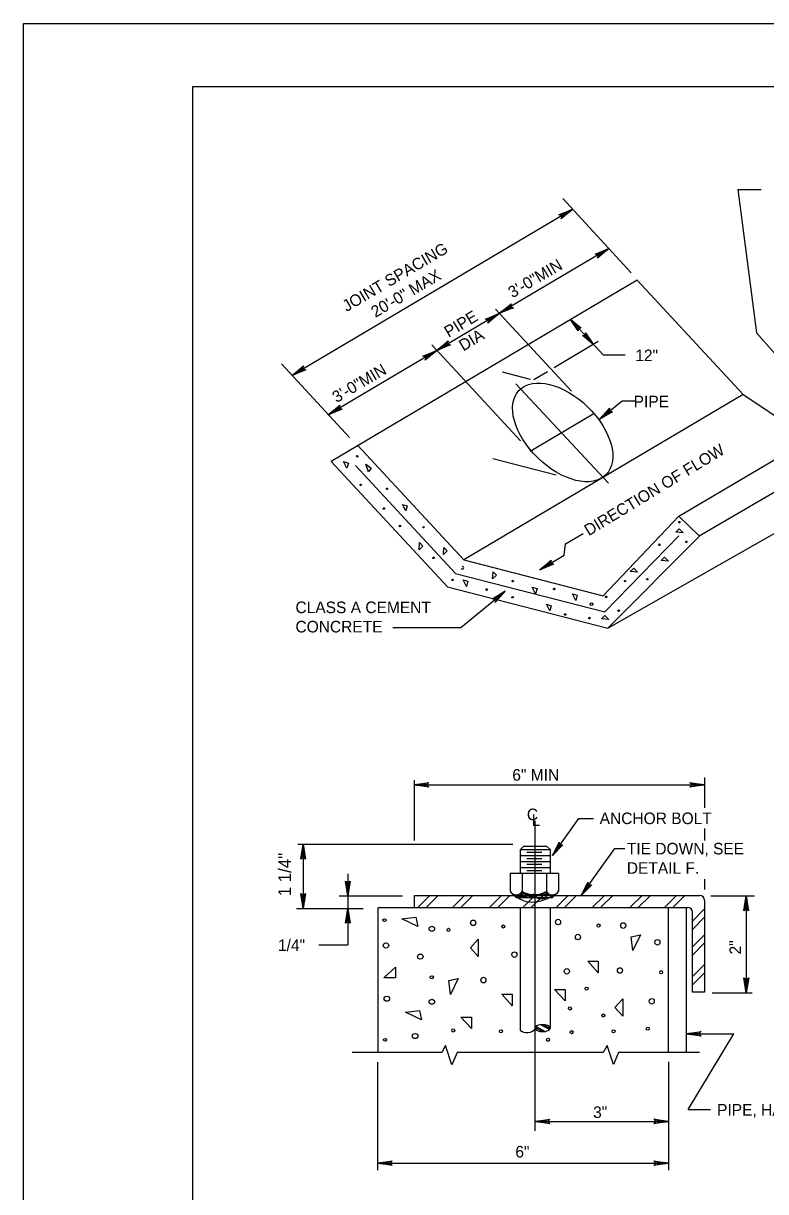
# Model space of a CAD drawing. Extents: x 5 to 910, y -47 to 547.
# Drawn here: x 4.7 to 180.3, y 270.9 to 547.5 of the extents above; entities that cross this region are included whole.
import ezdxf

# ---------------------------------------------------------------- set-up
doc = ezdxf.new("R2010")
doc.units = 0
for name, color, linetype in [('1', 7, 'Continuous'), ('2', 7, 'Continuous'), ('3', 7, 'Continuous'), ('PLT-BNDY', 7, 'Continuous')]:
    doc.layers.add(name, color=color, linetype=linetype)

msp = doc.modelspace()

# ---------------------------------------------------------------- linework, layer by layer
at = {"layer": '1'}
msp.add_lwpolyline([(830.72, -31.53), (830.72, 532.47), (44.72, 532.47), (44.72, -31.53), (830.72, -31.53), (830.72, -5.17), (630.72, -5.17), (630.72, 59.51), (830.72, 59.51), (830.72, 88.47), (630.72, 88.47), (630.72, -31.53), (709.52, -31.53), (709.52, -5.17), (709.52, -31.53), (786.52, -31.53), (786.52, -5.17), (786.52, -17.48), (830.72, -17.48)], dxfattribs=at)
for points in [[(81.6, 443.4), (81.25, 442.17), (80.45, 443.72)], [(85.76, 443.15), (87, 442.17), (86.38, 441.3)], [(95.53, 433.29), (95.19, 432.05), (94.39, 433.61)], [(159.86, 427.82), (160.78, 426.88), (159.04, 427.02)], [(99.21, 423.75), (98.3, 422.88), (98.41, 424.6)], [(104.98, 422.58), (104.06, 421.71), (104.18, 423.43)], [(156.39, 421.1), (157.3, 420.16), (155.56, 420.29)], [(116.62, 416.82), (115.71, 415.95), (115.82, 417.66)], [(149.09, 418.49), (150, 417.55), (148.26, 417.69)], [(109.87, 415.4), (109.53, 414.16), (108.73, 415.72)], [(126.21, 413.66), (125.87, 412.42), (125.07, 413.98)], [(135.73, 412.1), (135.38, 410.89), (134.58, 412.4)], [(129.57, 409.63), (129.23, 408.4), (128.43, 409.95)], [(142.27, 407.32), (143.19, 406.38), (141.45, 406.52)], [(94.25, 335.5), (97.56, 335.91), (98.02, 333.67)], [(112.32, 330.72), (112.32, 326.6), (110.44, 328.66)], [(148.88, 327.97), (148.47, 331.27), (150.71, 331.75)], [(92.76, 321.57), (89.99, 321.57), (92.76, 324.04)], [(140.71, 325.46), (140.71, 322.71), (138.24, 325.46)], [(105.73, 317.61), (105.32, 320.93), (107.58, 321.39)], [(132.84, 318.8), (132.84, 316.05), (130.37, 318.8)], [(120.33, 317.68), (120.33, 314.93), (117.86, 317.68)], [(146.5, 316.54), (146.5, 312.42), (144.65, 314.48)], [(95.09, 313.4), (98.41, 313.81), (98.87, 311.57)], [(110.7, 312.26), (110.7, 309.51), (108.23, 312.26)]]:
    msp.add_lwpolyline(points, close=True, dxfattribs=at)
for centre, major_axis in [((83.68, 445), (-0.132, 0.137)), ((84.52, 438.23), (-0.132, 0.137)), ((90.74, 437.29), (-0.116, 0.12)), ((89.98, 432.62), (-0.137, -0.132)), ((93.82, 428.5), (-0.137, -0.132)), ((159.85, 429.4), (0.131, -0.138)), ((99.37, 428.2), (-0.12, -0.116)), ((155.12, 424.05), (0.131, -0.138)), ((161.51, 424.73), (0.131, -0.138)), ((101.74, 420.96), (-0.137, -0.132)), ((106.2, 415.74), (-0.048, -0.184)), ((120.49, 415.45), (-0.048, -0.184)), ((147.01, 415.44), (-0.121, -0.115)), ((152.3, 415.89), (0.131, -0.138)), ((114.3, 413.43), (-0.048, -0.184)), ((130.28, 413.57), (-0.048, -0.184)), ((120.42, 411.61), (-0.042, -0.161)), ((139.08, 409.99), (-0.241, -0.229)), ((142.57, 411.72), (-0.048, -0.184)), ((132.87, 407.54), (-0.184, 0.048)), ((138.6, 406.69), (-0.048, -0.184)), ((145.53, 408.45), (-0.138, -0.131)), ((90.15, 335.19), (-0.381, 0)), ((111.11, 334.55), (0, -0.666)), ((131.19, 334.74), (0, -0.666)), ((101.33, 333.13), (-0.666, 0)), ((105.27, 332.87), (0, -0.381)), ((118.22, 333.69), (0, -0.381)), ((140.77, 333.9), (0, -0.381)), ((146.59, 333.91), (0, -0.666)), ((90.48, 329.18), (-0.666, 0)), ((135.88, 331.19), (0, -0.666)), ((154.68, 329.95), (0, -0.666)), ((98.6, 326.56), (-0.666, 0)), ((120.87, 327.03), (0, -0.666)), ((133.26, 323.07), (0, -0.666)), ((145.84, 323.27), (0, -0.666)), ((101.32, 321.67), (-0.381, 0)), ((113.54, 320.99), (0, -0.666)), ((155.59, 322.85), (0, -0.381)), ((137.95, 318.98), (0, -0.381)), ((90.69, 316.6), (-0.666, 0)), ((101.33, 315.86), (-0.666, 0)), ((153.36, 315.98), (0, -0.666)), ((133.99, 314.29), (0, -0.381)), ((141.88, 312.62), (0, -0.381)), ((152.4, 309.49), (0, -0.381)), ((90.26, 306.85), (-0.381, 0)), ((97.37, 307.76), (-0.666, 0)), ((106.4, 309.08), (0, -0.381)), ((117.67, 308.87), (0, -0.381)), ((128.83, 306.88), (0, -0.381)), ((134.39, 308.67), (0, -0.381)), ((144.33, 308.87), (0, -0.381))]:
    msp.add_ellipse(centre, major_axis=major_axis, ratio=0.9, dxfattribs=at)
msp.add_ellipse((108.57, 418.59), major_axis=(-0.322, 0.083), ratio=0.9, start_param=0.504724, end_param=5.232157, dxfattribs=at)
at = {"layer": '2'}
for p, q in [((173.7, 508.12), (179.24, 508.12)), ((134.65, 503.46), (68.26, 464.13)), ((132.3, 506.02), (148.49, 488.45)), ((143.23, 494.17), (117.33, 478.84)), ((149.91, 486.67), (77.52, 443.79)), ((149.91, 486.67), (174.96, 459.62)), ((117.29, 478.8), (102.48, 470.03)), ((116.42, 479.82), (134.35, 460.4)), ((134.17, 477.35), (141.87, 469.01)), ((178.09, 474.18), (208.3, 440.06)), ((101.36, 471.41), (122.32, 448.69)), ((140.71, 472.16), (130.24, 465.96)), ((102.48, 470.03), (76.84, 454.84)), ((141.87, 469.01), (147.07, 469.01)), ((65.76, 466.85), (81.85, 449.42)), ((117.95, 464.95), (124.61, 463.24)), ((128.68, 465.02), (125.45, 463.12)), ((159.77, 430.8), (219.81, 466.4)), ((121.24, 462.16), (143.12, 438.6)), ((174.96, 459.62), (108.87, 420.48)), ((174.96, 459.62), (190.66, 449.12)), ((141.03, 453.77), (146.34, 458.11)), ((146.34, 458.11), (149.36, 458.11)), ((164.58, 426.13), (217.93, 457.43)), ((139.5, 454.93), (124.63, 446.12)), ((83.82, 447.52), (108.87, 420.48)), ((77.52, 443.79), (105.02, 414.09)), ((83.31, 442.83), (106.97, 417.27)), ((115.73, 444.45), (130.76, 440.59)), ((142.36, 441.05), (142.36, 441.05)), ((142.93, 404.33), (196.77, 434.94)), ((159.77, 430.8), (141.84, 411.97)), ((159.77, 430.8), (164.65, 426.06)), ((132.94, 424.25), (137.1, 426.72)), ((159.73, 426.13), (142.22, 408.19)), ((164.65, 426.06), (142.93, 404.33)), ((132.64, 421.55), (132.98, 424.28)), ((108.87, 420.48), (141.84, 411.97)), ((126.85, 418.14), (132.64, 421.55)), ((106.97, 417.27), (142.22, 408.19)), ((105.02, 414.09), (142.93, 404.33)), ((108.23, 404.44), (118.71, 413.07)), ((92.14, 404.44), (108.23, 404.44)), ((97.13, 368.31), (97.13, 354.03)), ((165.86, 368.95), (165.86, 361.74)), ((97.13, 367.23), (165.86, 367.23)), ((125.77, 285.29), (125.77, 358.7)), ((129.85, 350.49), (136.11, 359.25)), ((136.11, 359.25), (139.61, 359.25)), ((165.86, 356.85), (165.86, 354.08)), ((69.61, 353.16), (120.49, 353.16)), ((70.91, 353.16), (70.91, 337.97)), ((122.2, 351.95), (129.34, 351.95)), ((122.2, 351.95), (122.2, 346.37)), ((122.3, 351.95), (123.1, 352.68)), ((123.1, 352.68), (128.45, 352.68)), ((123.78, 351.27), (127.33, 351.27)), ((129.34, 351.95), (128.45, 352.68)), ((129.34, 351.95), (129.34, 346.44)), ((136.65, 341.02), (144.6, 352.12)), ((144.6, 352.12), (146.96, 352.12)), ((122.2, 350.53), (129.34, 350.53)), ((122.2, 349.09), (129.34, 349.09)), ((123.78, 349.82), (127.33, 349.82)), ((81.46, 346.19), (81.46, 340.92)), ((131.29, 346.23), (119.85, 346.23)), ((119.85, 346.23), (119.85, 342)), ((122.2, 347.67), (129.34, 347.67)), ((122.71, 346.23), (122.71, 341.98)), ((123.78, 348.41), (127.33, 348.41)), ((123.78, 346.96), (127.33, 346.96)), ((128.43, 346.23), (128.43, 341.98)), ((131.29, 346.23), (131.29, 342.02)), ((165.86, 344.88), (165.86, 342.41)), ((79.42, 340.92), (94.38, 340.92)), ((81.46, 340.92), (81.46, 329.32)), ((97.2, 338.16), (97.2, 341.02)), ((97.2, 341.02), (164.74, 341.02)), ((98, 338.16), (100.86, 341.02)), ((99.97, 338.16), (102.83, 341.02)), ((106.21, 338.16), (109.07, 341.02)), ((108.18, 338.16), (111.04, 341.02)), ((114.97, 338.16), (117.83, 341.02)), ((116.94, 338.16), (119.8, 341.02)), ((120.37, 341.45), (121.29, 340.51)), ((121.29, 340.51), (129.85, 340.51)), ((122.84, 338.16), (125.7, 341.02)), ((124.81, 338.16), (127.67, 341.02)), ((130.76, 341.45), (129.85, 340.51)), ((130.74, 338.16), (133.6, 341.02)), ((132.71, 338.16), (135.57, 341.02)), ((139.29, 338.16), (142.15, 341.02)), ((141.26, 338.16), (144.12, 341.02)), ((148.19, 338.16), (151.05, 341.02)), ((150.16, 338.16), (153.02, 341.02)), ((156.36, 338.16), (159.22, 341.02)), ((158.33, 338.16), (161.19, 341.02)), ((167.34, 340.92), (177.62, 340.92)), ((175.72, 340.92), (175.72, 318.02)), ((69.31, 337.97), (85.12, 337.97)), ((88.6, 338.16), (161.88, 338.16)), ((88.6, 303.84), (88.6, 338.16)), ((122.2, 338.02), (122.2, 309.12)), ((129.34, 338.06), (129.34, 309.6)), ((157.23, 338.16), (157.23, 303.84)), ((161.51, 338.16), (161.51, 303.84)), ((162.97, 334.98), (165.83, 337.84)), ((165.83, 339.92), (165.83, 318.14)), ((162.97, 318.14), (162.97, 337.06)), ((162.97, 333.01), (165.83, 335.87)), ((74.62, 329.32), (81.46, 329.32)), ((162.97, 328.89), (165.83, 331.75)), ((162.97, 326.92), (165.83, 329.78)), ((162.97, 321.82), (165.83, 324.68)), ((162.97, 319.85), (165.83, 322.71)), ((165.83, 318.14), (162.97, 318.14)), ((167.64, 318.02), (177.09, 318.02)), ((125.8, 309.74), (127.56, 308.8)), ((125.98, 310.02), (128.15, 308.85)), ((127.05, 310.45), (129.14, 309.28)), ((127.65, 310.47), (129.32, 309.53)), ((161.51, 308.28), (172.73, 308.28)), ((103.72, 303.84), (82.46, 303.84)), ((88.46, 301.6), (88.46, 275.97)), ((141.88, 303.84), (107.36, 303.84)), ((164.64, 303.84), (145.52, 303.84)), ((157.32, 301.66), (157.32, 275.97)), ((161.95, 290.4), (167.28, 290.4)), ((125.77, 287.55), (157.32, 287.55)), ((88.46, 277.64), (157.32, 277.64))]:
    msp.add_line(p, q, dxfattribs=at)
for points in [[(175.31, 337.61), (175.53, 337.72), (175.72, 340.92), (175.31, 337.61), (175.15, 337.42), (175.72, 340.92), (175.88, 337.72), (176.11, 337.61), (175.72, 340.92), (176.27, 337.42), (176.11, 337.61)], [(107.36, 303.84), (106.1, 300.96), (104.59, 305.49), (103.72, 303.84)], [(145.52, 303.84), (144.28, 301), (142.77, 305.53), (141.88, 303.84)]]:
    msp.add_lwpolyline(points, dxfattribs=at)
for centre, radius, start, end in [((121.29, 342.82), 1.65, 209.0546, 331.645), ((125.53, 347.1), 5.88, 241.013, 299.4435), ((129.84, 342.82), 1.65, 211.9209, 330.9454), ((164.73, 339.92), 1.1, 0, 90), ((161.87, 337.06), 1.1, 0, 90)]:
    msp.add_arc(centre, radius, start, end, dxfattribs=at)
msp.add_ellipse((132.29, 450.65), major_axis=(10.28, -9.99), ratio=0.58964, dxfattribs=at)
for centre, major_axis, start_param, end_param in [((127.53, 309.45), (-1.88, 0), 3.352555, 6.084645), ((123.86, 309.62), (-1.87, 0), 0.486014, 2.941111), ((127.53, 309.82), (1.87, 0), 3.308332, 6.128868)]:
    msp.add_ellipse(centre, major_axis=major_axis, ratio=0.546749, start_param=start_param, end_param=end_param, dxfattribs=at)
for points in [[(121.01, 341.06), (121.47, 340.67), (129.57, 340.74), (130.21, 341.13), (129.34, 341.06), (128.79, 341.22), (128.43, 341.52), (128.34, 341.7), (127.51, 341.38), (126.51, 341.11), (125.86, 341.08), (125.89, 340.88), (128.38, 340.9), (128.31, 341.15), (127.03, 341.08), (128.24, 341.45), (128.79, 340.97)], [(121.29, 341.08), (121.59, 340.88), (125.38, 340.88), (125.52, 340.92), (125.54, 341.11), (124.77, 341.15), (123.92, 341.2), (123.37, 341.47), (122.71, 341.68), (122.18, 341.27), (121.82, 341.11), (121.47, 341.08), (121.61, 340.97), (123.85, 341.04), (122.89, 341.34), (122.32, 341.2), (122.78, 341.18)]]:
    msp.add_spline(points, degree=3, dxfattribs=at)
at = {"layer": '3'}
for p, q in [((173.7, 508.12), (178.09, 474.18)), ((161.95, 290.4), (172.73, 308.28))]:
    msp.add_line(p, q, dxfattribs=at)
for points in [[(131.59, 502.13), (131.81, 501.97), (134.65, 503.46), (131.59, 502.13), (131.36, 502.15), (134.65, 503.46), (131.97, 501.7), (132, 501.42), (134.65, 503.46), (131.93, 501.19), (132, 501.42)], [(140.17, 492.84), (140.39, 492.68), (143.23, 494.17), (140.17, 492.84), (139.94, 492.87), (143.23, 494.17), (140.55, 492.41), (140.58, 492.13), (143.23, 494.17), (140.51, 491.9), (140.58, 492.13)], [(114.22, 477.47), (114.45, 477.31), (117.29, 478.8), (114.22, 477.47), (113.99, 477.49), (117.29, 478.8), (114.61, 477.03), (114.63, 476.76), (117.29, 478.8), (114.56, 476.53), (114.63, 476.76)], [(120.4, 480.17), (120.17, 480.33), (117.33, 478.84), (120.4, 480.17), (120.63, 480.15), (117.33, 478.84), (120.01, 480.6), (119.99, 480.88), (117.33, 478.84), (120.06, 481.11), (119.99, 480.88)], [(135.91, 474.91), (136, 475.13), (134.17, 477.35), (135.91, 474.91), (135.93, 474.7), (134.17, 477.35), (136.23, 475.34), (136.46, 475.41), (134.17, 477.35), (136.67, 475.39), (136.46, 475.41)], [(137.72, 474.04), (137.65, 473.81), (139.48, 471.57), (137.72, 474.04), (137.69, 474.24), (139.48, 471.57), (137.42, 473.6), (137.19, 473.53), (139.48, 471.57), (136.99, 473.56), (137.19, 473.53)], [(105.55, 471.36), (105.32, 471.52), (102.48, 470.03), (105.55, 471.36), (105.78, 471.34), (102.48, 470.03), (105.16, 471.79), (105.14, 472.07), (102.48, 470.03), (105.21, 472.3), (105.14, 472.07)], [(99.42, 468.71), (99.65, 468.55), (102.48, 470.03), (99.42, 468.71), (99.19, 468.73), (102.48, 470.03), (99.81, 468.27), (99.83, 468), (102.48, 470.03), (99.76, 467.77), (99.83, 468)], [(71.32, 465.46), (71.09, 465.62), (68.26, 464.13), (71.32, 465.46), (71.55, 465.43), (68.26, 464.13), (70.93, 465.89), (70.91, 466.17), (68.26, 464.13), (70.98, 466.4), (70.91, 466.17)], [(79.9, 456.17), (79.67, 456.33), (76.84, 454.84), (79.9, 456.17), (80.13, 456.15), (76.84, 454.84), (79.51, 456.6), (79.49, 456.88), (76.84, 454.84), (79.56, 457.11), (79.49, 456.88)], [(143.87, 455.55), (143.62, 455.67), (141.03, 453.77), (143.87, 455.55), (144.1, 455.55), (141.03, 453.77), (143.41, 455.92), (143.35, 456.17), (141.03, 453.77), (143.39, 456.42), (143.35, 456.17)], [(129.92, 419.47), (129.69, 419.63), (126.85, 418.14), (129.92, 419.47), (130.14, 419.45), (126.85, 418.14), (129.53, 419.91), (129.5, 420.18), (126.85, 418.14), (129.57, 420.41), (129.5, 420.18)], [(115.87, 411.28), (116.12, 411.17), (118.71, 413.07), (115.87, 411.28), (115.64, 411.28), (118.71, 413.07), (116.33, 410.91), (116.39, 410.66), (118.71, 413.07), (116.35, 410.41), (116.39, 410.66)], [(100.45, 366.82), (100.33, 367.05), (97.13, 367.23), (100.45, 366.82), (100.63, 366.66), (97.13, 367.23), (100.33, 367.39), (100.45, 367.62), (97.13, 367.23), (100.63, 367.78), (100.45, 367.62)], [(162.54, 367.65), (162.65, 367.42), (165.86, 367.23), (162.54, 367.65), (162.36, 367.81), (165.86, 367.23), (162.65, 367.07), (162.54, 366.85), (165.86, 367.23), (162.36, 366.69), (162.54, 366.85)], [(70.5, 349.85), (70.73, 349.96), (70.91, 353.16), (70.5, 349.85), (70.34, 349.66), (70.91, 353.16), (71.07, 349.96), (71.3, 349.85), (70.91, 353.16), (71.46, 349.66), (71.3, 349.85)], [(132.11, 352.96), (131.86, 352.98), (129.85, 350.49), (132.11, 352.96), (132.34, 353), (129.85, 350.49), (131.58, 353.19), (131.45, 353.42), (129.85, 350.49), (131.42, 353.64), (131.45, 353.42)], [(81.87, 344.24), (81.64, 344.13), (81.46, 340.92), (81.87, 344.24), (82.03, 344.42), (81.46, 340.92), (81.3, 344.13), (81.07, 344.24), (81.46, 340.92), (80.91, 344.42), (81.07, 344.24)], [(138.91, 343.49), (138.66, 343.51), (136.65, 341.02), (138.91, 343.49), (139.14, 343.53), (136.65, 341.02), (138.39, 343.72), (138.25, 343.94), (136.65, 341.02), (138.23, 344.17), (138.25, 343.94)], [(71.32, 341.29), (71.09, 341.18), (70.91, 337.97), (71.32, 341.29), (71.48, 341.47), (70.91, 337.97), (70.75, 341.18), (70.52, 341.29), (70.91, 337.97), (70.36, 341.47), (70.52, 341.29)], [(81.05, 334.66), (81.27, 334.77), (81.46, 337.97), (81.05, 334.66), (80.89, 334.47), (81.46, 337.97), (81.62, 334.77), (81.85, 334.66), (81.46, 337.97), (82.01, 334.47), (81.85, 334.66)], [(176.13, 321.34), (175.9, 321.23), (175.72, 318.02), (176.13, 321.34), (176.29, 321.52), (175.72, 318.02), (175.56, 321.23), (175.33, 321.34), (175.72, 318.02), (175.17, 321.52), (175.33, 321.34)], [(164.83, 307.86), (164.71, 308.09), (161.51, 308.28), (164.83, 307.86), (165.01, 307.7), (161.51, 308.28), (164.71, 308.44), (164.83, 308.67), (161.51, 308.28), (165.01, 308.83), (164.83, 308.67)], [(129.09, 287.14), (128.98, 287.37), (125.77, 287.55), (129.09, 287.14), (129.27, 286.98), (125.77, 287.55), (128.98, 287.71), (129.09, 287.94), (125.77, 287.55), (129.27, 288.1), (129.09, 287.94)], [(154.01, 287.96), (154.12, 287.73), (157.32, 287.55), (154.01, 287.96), (153.82, 288.12), (157.32, 287.55), (154.12, 287.39), (154.01, 287.16), (157.32, 287.55), (153.82, 287), (154.01, 287.16)], [(91.78, 277.23), (91.66, 277.46), (88.46, 277.64), (91.78, 277.23), (91.96, 277.07), (88.46, 277.64), (91.66, 277.8), (91.78, 278.03), (88.46, 277.64), (91.96, 278.19), (91.78, 278.03)], [(154.01, 278.05), (154.12, 277.82), (157.32, 277.64), (154.01, 278.05), (153.82, 278.21), (157.32, 277.64), (154.12, 277.48), (154.01, 277.25), (157.32, 277.64), (153.82, 277.09), (154.01, 277.25)]]:
    msp.add_lwpolyline(points, dxfattribs=at)
at = {"layer": 'PLT-BNDY'}
msp.add_lwpolyline([(4.72, 547.47), (845.72, 547.47), (845.72, -46.53), (4.72, -46.53)], close=True, dxfattribs=at)

# ---------------------------------------------------------------- texts
at = {"layer": '2'}
for s, height, p in [('CLASS A CEMENT', 2.7454, (69.08, 407.86)), ('CONCRETE', 2.745, (69.08, 403.29))]:
    msp.add_text(s, height=height, dxfattribs=at).set_placement(p)
msp.add_text('1 1/4"', height=2.997, rotation=90, dxfattribs=at).set_placement((68.03, 340.81))
at = {"layer": '3'}
for s, height, rotation, p in [(' JOINT SPACING', 2.7455, 30.4871, (80.32, 478.59)), ('3\'-0"MIN', 2.745, 30.4871, (120.41, 482.36)), ('20\'-0" MAX', 2.745, 30.4871, (87.98, 477.74)), ('PIPE', 2.745, 31, (105.31, 473.01)), ('DIA', 2.745, 31, (108.77, 469.78)), ('3\'-0"MIN', 2.745, 30.4871, (78.8, 457.56)), (' DIRECTION OF FLOW', 2.7454, 31.2871, (137.58, 425.51)), ('2"', 2.745, 90, (174.48, 327.06))]:
    msp.add_text(s, height=height, rotation=rotation, dxfattribs=at).set_placement(p)
for s, height, p in [('12"', 2.745, (149.46, 467.51)), (' PIPE', 2.745, (148.06, 456.6)), ('6" MIN', 2.745, (120.37, 368.2)), ('C', 2.75, (123.81, 358.84)), ('L', 2.75, (124.95, 357.47)), ('ANCHOR BOLT', 2.7454, (141.03, 357.92)), ('TIE DOWN, SEE', 2.7454, (147.46, 350.74)), ('DETAIL F.', 2.745, (147.46, 346.16)), ('1/4"', 2.745, (64.94, 327.88)), ('3"', 2.745, (139.48, 288.35)), ('PIPE, HALF-CIRCLE', 2.7454, (168.81, 288.92)), ('6"', 2.745, (121.09, 278.99))]:
    msp.add_text(s, height=height, dxfattribs=at).set_placement(p)

doc.saveas('drawing.dxf')
